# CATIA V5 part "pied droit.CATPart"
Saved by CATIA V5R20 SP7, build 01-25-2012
Part number: pied droit bati
Bounding box of the stored display mesh (mm): x -30.69 to -6.692, y 42.178 to 67.258, z -51.024 to -26.692
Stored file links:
  F:\Travaux\Modélisations\CFAO_2011\CFAO_2011_MMS\CFAO_2011_MMS_DONE\CFAO_2011_MMS_jboiteux\Catia\pied droit.CATPart
  U:\finthinkmotion\stepper.CATProduct
  F:\Travaux\Modélisations\CFAO_2011\CFAO_2011_MMS\CFAO_2011_MMS_DONE\CFAO_2011_MMS_jboiteux\Catia\bati.CATPart
  F:\Travaux\Modélisations\CFAO_2011\CFAO_2011_MMS\CFAO_2011_MMS_DONE\CFAO_2011_MMS_jboiteux\Catia\Part1.CATPart
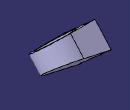
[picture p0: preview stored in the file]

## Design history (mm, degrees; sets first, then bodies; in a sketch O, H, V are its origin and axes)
Parameters
  `rayon tube` = 9 mm {= External.royontubebati}
External parameters (linked from other documents)
  External.royontubebati = 9 mm
Set1
  DatumSurface1: linked copy from another document
  DatumCurve1: linked copy from another document
  Line1: linked copy from another document
  Line2: linked copy from another document
Body1 (main body)
  Sketch1 on face of DatumSurface1, origin (0, 41.7857, -47.0089), H (-1, 0, 0), V (0, 0.7474, 0.6644)
    projected circle E1 centre (17.69, 15.0811) radius 9 from edge of DatumCurve1
    point P1 (17.69, 15.0811)
    arc A1 centre (17.69, 15.0811) radius 11 from (17.69, 26.0811) to (17.69, 4.0811) ccw
    line L1 (17.69, 26.0811) -> (30.69, 26.0811)
    line L2 (30.69, 26.0811) -> (30.69, 24.8588)
    line L3 (30.69, 24.8588) -> (28.69, 23.6366)
    point P6 (28.69, 23.6366)
    line L4 (28.69, 23.6366) -> (28.69, 21.1922)
    line L5 (28.69, 21.1922) -> (30.69, 19.9699)
    point P8 (30.69, 19.9699)
    line L6 (30.69, 19.9699) -> (30.69, 17.5255)
    line L7 (30.69, 17.5255) -> (28.69, 16.3033)
    point P10 (28.69, 16.3033)
    line L8 (28.69, 16.3033) -> (28.69, 13.8588)
    point P11 (28.69, 13.8588)
    line L9 (28.69, 13.8588) -> (30.69, 12.6366)
    point P12 (30.69, 12.6366)
    line L10 (30.69, 12.6366) -> (30.69, 10.1922)
    point P13 (30.69, 10.1922)
    line L11 (30.69, 10.1922) -> (28.69, 8.9699)
    point P14 (28.69, 8.9699)
    line L12 (28.69, 8.9699) -> (28.69, 6.5255)
    point P15 (28.69, 6.5255)
    line L13 (28.69, 6.5255) -> (30.69, 5.3033)
    point P16 (30.69, 5.3033)
    line L14 (30.69, 5.3033) -> (30.69, 4.0811)
    line L15 (30.69, 4.0811) -> (17.69, 4.0811)
    reference projected line E2 (17.69, -40.5262) -> (17.69, 13.2873) from Line1
    reference projected line E3 (17.69, 68.8945) -> (17.69, -2.8568) from Line2
    radius A1 = 11 {= `rayon tube`+2mm}
    length L2 = 1.2222 {= (2mm+`rayon tube` )/9}
    length L4 = 2.4444 {= (`rayon tube`+2mm) /4.5}
    length L8 = 2.4444 {= (`rayon tube`+2mm) /4.5}
    length L6 = 2.4444 {= (`rayon tube`+2mm) /4.5}
    length L12 = 2.4444 {= (`rayon tube`+2mm) /4.5}
    length L14 = 1.2222 {= (`rayon tube`+2mm )/9}
    distance P15 L14 = 2
    distance P15 L15 = 2.4444 {= (`rayon tube`+2mm) /4.5}
    length L10 = 2.4444 {= (`rayon tube`+2mm) /4.5}
    distance P13 L15 = 6.1111 {= (`rayon tube` +2mm) *2*5/18}
    distance P6 L1 = 2.4444 {= (`rayon tube`+2mm )*4/18}
    distance P8 L1 = 6.1111 {= (`rayon tube`+2mm) *10/18}
    distance P10 L1 = 9.7778 {= (`rayon tube` +2mm)*16/18}
    distance P11 L15 = 9.7778 {= (`rayon tube` +2mm)*16/18}
    distance E2 L8 = 11 {= `rayon tube` +2mm}
    angle E3 L1 = 90
    concentricity: P1 E1
    tangency: L1 A1, L15 A1
    vertical: L2 V, L4 V, L6 V, L8 V, L10 V, L12 V, L14 V
    coincidence: P8 L2, P10 L4, P12 L2, P14 L4, P16 L2
  Pad1: profile Sketch1, direction (0, -0.6644, 0.7474), length 4
  Sketch2 on start face of Pad1, origin (0, 41.7857, -47.0089), H (-1, 0, 0), V (0, 0.7474, 0.6644)
    projected arc E1 centre (17.69, 15.0811) radius 11 from (17.69, 26.0811) to (17.69, 4.0811) ccw from edge [face of Pad1 from Sketch1.A1 | start face of Pad1]
    projected line E2 (17.69, 4.0811) -> (30.69, 4.0811) from edge [face of Pad1 from Sketch1.L15 | start face of Pad1]
    projected line E3 (30.69, 4.0811) -> (30.69, 5.3033) from edge [face of Pad1 from Sketch1.L14 | start face of Pad1]
    projected line E4 (30.69, 5.3033) -> (28.69, 6.5255) from edge [face of Pad1 from Sketch1.L13 | start face of Pad1]
    projected line E5 (28.69, 6.5255) -> (28.69, 8.9699) from edge [face of Pad1 from Sketch1.L12 | start face of Pad1]
    projected line E6 (28.69, 8.9699) -> (30.69, 10.1922) from edge [face of Pad1 from Sketch1.L11 | start face of Pad1]
    projected line E7 (30.69, 10.1922) -> (30.69, 12.6366) from edge [face of Pad1 from Sketch1.L10 | start face of Pad1]
    projected line E8 (30.69, 12.6366) -> (28.69, 13.8588) from edge [face of Pad1 from Sketch1.L9 | start face of Pad1]
    projected line E9 (28.69, 13.8588) -> (28.69, 16.3033) from edge [face of Pad1 from Sketch1.L8 | start face of Pad1]
    projected line E10 (28.69, 16.3033) -> (30.69, 17.5255) from edge [face of Pad1 from Sketch1.L7 | start face of Pad1]
    projected line E11 (30.69, 17.5255) -> (30.69, 19.9699) from edge [face of Pad1 from Sketch1.L6 | start face of Pad1]
    projected line E12 (30.69, 19.9699) -> (28.69, 21.1922) from edge [face of Pad1 from Sketch1.L5 | start face of Pad1]
    projected line E13 (28.69, 21.1922) -> (28.69, 23.6366) from edge [face of Pad1 from Sketch1.L4 | start face of Pad1]
    projected line E14 (28.69, 23.6366) -> (30.69, 24.8588) from edge [face of Pad1 from Sketch1.L3 | start face of Pad1]
    projected line E15 (30.69, 24.8588) -> (30.69, 26.0811) from edge [face of Pad1 from Sketch1.L2 | start face of Pad1]
    projected line E16 (30.69, 26.0811) -> (17.69, 26.0811) from edge [face of Pad1 from Sketch1.L1 | start face of Pad1]
  Pad2: profile Sketch2, direction (0, 0.6644, -0.7474), length 9 {= `rayon tube`}
  Point1: type OnCurve, Support edge [face of Pad2 | end face of Pad2], Ratio 0
  Point2: type OnCurve, Support edge [face of Pad2 | end face of Pad2], Ratio 0
  Plane1: type Offset, RefPlane end face of Pad2, Offset 0
  Line3: type PtPt, FirstPoint Point1, SecondPoint Point2
  Plane2: type Angle, RefPlane Plane1, Direction Line3, Angle -10
  Split1: SplitPlane Plane2
Relations
  Sketch1.distance(P15 L14) = `rayon tube` /4.5 (deactivated)
  Pad1.FirstLimit.Length = `rayon tube` *1.5 (deactivated)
